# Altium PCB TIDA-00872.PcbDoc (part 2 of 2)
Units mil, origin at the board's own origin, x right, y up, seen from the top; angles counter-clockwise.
Board outline 2300 x 2250 mil, 2 copper layers (Top Layer, Bottom Layer), stack 64.8 mil thick; 81 components, 62 nets, 253 pads, 305 vias.
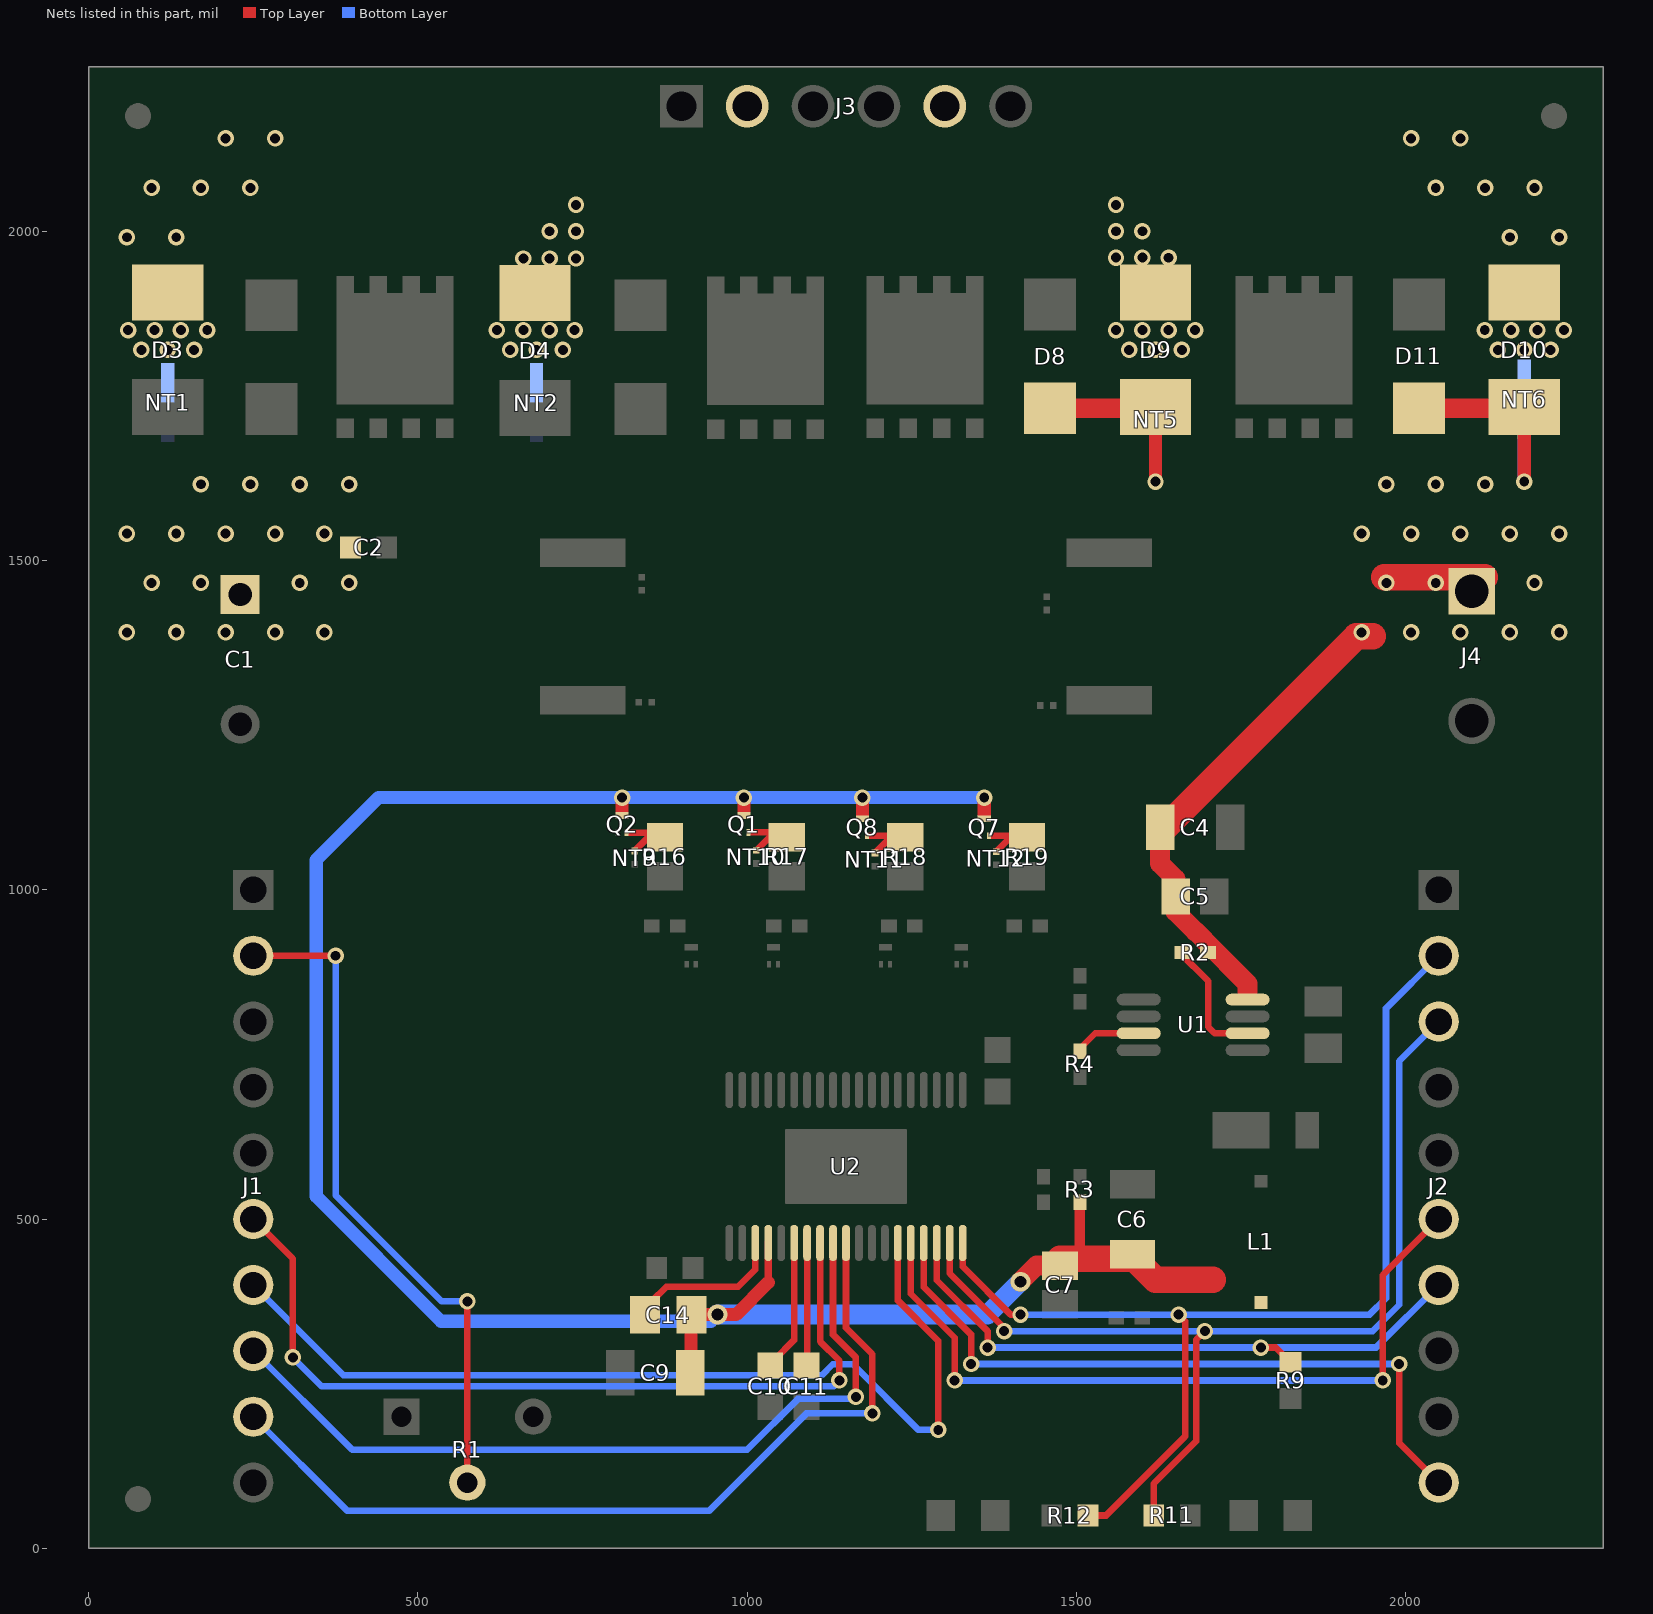
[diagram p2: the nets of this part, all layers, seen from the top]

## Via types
v1: diameter 25, hole 15, Top Layer to Bottom Layer, tented both sides, 286 vias
v2: diameter 19.68, hole 7.87, Top Layer to Bottom Layer, tented both sides, 12 vias
v3: diameter 50, hole 31, Top Layer to Bottom Layer, tented both sides, 2 vias
v4: diameter 26, hole 15, Top Layer to Bottom Layer, tented both sides, 2 vias
v5: diameter 30, hole 18, Top Layer to Bottom Layer, tented both sides, 2 vias
v6: diameter 25, hole 15, Top Layer to Bottom Layer, 1 vias

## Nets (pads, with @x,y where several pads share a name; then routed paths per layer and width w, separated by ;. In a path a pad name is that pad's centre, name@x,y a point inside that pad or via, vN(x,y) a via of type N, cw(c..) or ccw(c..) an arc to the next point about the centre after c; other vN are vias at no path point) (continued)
NetD8_1: D8.1 D9.1 NT5.1 | length 293.4
  Top Layer w20: D9.1@1618.27,1731.26 D9.1@1620,1732.99 ; v1(1620,1620) 1620,1688.99
  Top Layer w30: D8.1@1460,1731.26 D9.1@1618.27,1731.26
  Bottom Layer w20: v1(1620,1620) 1620,1630 NT5.1@1619.99,1683.7
NetD10_1: D10.1 D11.1 NT6.2 | length 337.2
  Top Layer w20: D10.1@2178.27,1731.26 D10.1@2180,1732.99 v1(2180,1620)
  Top Layer w30: D11.1@2020,1731.26 D10.1@2178.27,1731.26
  Bottom Layer w20: v1(2180,1620) 2180,1683.5
NetNT9_2: NT9.2 Q2.2 R16.2 | length 115.8
  Top Layer w6: R16.2@849.53,1079.53 R16.2@875,1079.53 R16.2@867.32,1087.2
  Top Layer w10: Q2.2@819,1087 R16.2@869.43,1087 ; NT9.2@829,1059 R16.2@849.53,1079.53
NetNT10_2: NT10.2 Q1.2 R17.2 | length 93.1
  Top Layer w10: 1006.54,1087.2 R17.2@1041.2,1087.2 ; NT10.2@1014,1060 R17.2@1041.2,1087.2 ; R17.2@1060,1090 1044,1090 R17.2@1041.2,1087.2
NetNT11_2: NT11.2 Q8.2 R18.2 | length 83.5
  Top Layer w10: Q8.2@1184.54,1082 R18.2@1220,1082 ; NT11.2@1194,1056 R18.2@1220,1082 ; R18.2@1228,1090 R18.2@1220,1082
NetNT12_2: NT12.2 Q7.2 R19.2 | length 91.8
  Top Layer w10: Q7.2@1369,1082 R19.2@1400.57,1082 ; NT12.2@1378,1058 1403.11,1083.11 1410,1090 R19.2@1425,1090
NetR2_2: R2.2 U1.6 | length 195.1
  Top Layer w10: R2.2@1656.38,905 1700,861.38 1700,791.85 1709.65,782.2 U1.6@1759.84,782.2
NetR4_2: R4.2 U1.3 | length 99.3
  Top Layer w10: R4.2@1505,758.62 1528.58,782.2 U1.3@1594.49,782.2
NFAULT: J2.3 R11.2 U2.18 | length 1558.5
  Top Layer w10: U2.18@1307.48,470.75 1307.48,417.52 1390,335 v1(1390,330) ; R11.2@1617.44,50 1617.44,98.4 1682,162.96 1682,317 v1(1695,330)
  Bottom Layer w10: v1(1390,330) v1(1695,330) 1950,330 1990,370 1990,740 J2.3@2050,800
NSLEEP: J1.6 U2.8 | length 1314.7
  Top Layer w10: J1.6@250,500 310,440 v1(310,290) ; U2.8@1110.63,470.75 1110.63,314.37 1140,285 v1(1140,255)
  Bottom Layer w10: v1(310,290) 354,246 1131,246 v1(1140,255)
NSTALL: J2.2 R12.1 U2.19 | length 1660.7
  Top Layer w10: U2.19@1327.17,470.75 1327.17,427.83 1400,355 v1(1415,355) ; R12.1@1522.56,50 1545,50 1665,170 1665,345 v1(1655,355)
  Bottom Layer w10: v1(1415,355) 1945,355 1970,380 1970,820 J2.2@2050,900
POT: J1.2 R1.2 | length 1030.6
  Top Layer w10: J1.2@250,900 v1(375,900) ; R1.2@575,100 v1(575,375)
  Bottom Layer w10: v1(375,900) 375,536.11 536.11,375 v1(575,375)
RESET: J1.8 U2.9 | length 1270.4
  Top Layer w10: U2.9@1130.31,475.75 1130.31,324.69 1165,290 v1(1165,230)
  Bottom Layer w10: J1.8@250,300 400,150 1000.11,150 1077.11,227 1162,227 v1(1165,230)
SCLK: J1.7 U2.14 | length 1460.9
  Top Layer w10: U2.14@1228.74,470.75 1228.74,376.26 1290,315 v1(1290,180)
  Bottom Layer w10: J1.7@250,400 387,263 1113.35,263 1129.85,279.5 1160.5,279.5 1260,180 v1(1290,180)
SCS: J2.10 U2.16 | length 1070.4
  Top Layer w10: U2.16@1268.11,470.75 1268.11,396.89 1340,325 v1@1340,285 ; v1(1990,280) 1990,160 J2.10@2050,100
  Bottom Layer w10: v1(1340,280) v1(1990,280)
SDATI: J2.6 U2.15 | length 1173.5
  Top Layer w10: U2.15@1248.43,470.75 1248.43,386.57 1315,320 v1(1315,255) ; v1(1965,255) 1965,415 J2.6@2050,500
  Bottom Layer w10: v1(1315,255) v1(1965,255)
SDATO: J2.7 R9.1 U2.17 | length 966.4
  Top Layer w10: U2.17@1287.8,470.75 1287.8,407.2 1365,330 v1@1365,315 ; v1(1780,305) 1802.56,305 R9.1@1825,282.56
  Bottom Layer w10: v1(1365,305) v1(1780,305) 1955,305 J2.7@2050,400
STEP/AIN1: J1.9 U2.10 | length 1342.9
  Top Layer w10: U2.10@1150,470.75 1150,335 1190,295 v1(1190,205)
  Bottom Layer w10: J1.9@250,200 393,57 942,57 1090,205 v1(1190,205)
V5: C10.1 U2.6 | length 211.7
  Top Layer w10: C10.1@1041,271.56 1041,286 1071.26,316.26 U2.6@1071.26,463.86 U2.6@1071.26,470.75
V12: C6.1 C7.1 C9.1 C14.2 L1.2 Q1.3 Q2.3 Q7.3 Q8.3 R3.2 U2.4 | length 3508.2
  Top Layer w12: 1031.89,403.89 U2.4@1031.89,463.86
  Top Layer w16: 1505,441.5 R3.2@1505,525.31
  Top Layer w20: 810,1119.41 v1(810,1140) ; C9.1@918.15,275 914.53,278.62 914.53,355 v5(955,355) 983,355 1031.89,403.89 ; 995,1119.41 v1(995,1140) ; 1175,1114.41 v1(1175,1140) ; 1360,1114.41 v1(1360,1140)
  Top Layer w30: v5(1415,405) 1439.53,429.53 C7.1@1475,429.53
  Top Layer w40: C7.1@1475,440 1587.91,440 1619.91,408 1707,408
  Bottom Layer w20: v5(955,355) 945,345 535,345 345.5,534.5 345.5,1045.5 440,1140 v1(810,1140) v1(995,1140) v1(1175,1140) v1(1360,1140)
  Bottom Layer w30: v5(955,355) 1365,355 v5(1415,405)
VCP: C14.1 U2.3 | length 244.5
  Top Layer w10: C14.1@855.47,355 855.47,375.47 877.27,397.27 986.16,397.27 1012.2,423.32 U2.3@1012.2,463.86 U2.3@1012.2,470.75
VINT: C11.1 U2.7 | length 197.2
  Top Layer w10: C11.1@1090.94,273.5 U2.7@1090.94,470.75
VM: C1.1 C2.1 C4.1 C5.1 D3.2 D4.2 D9.2 D10.2 J3.2 J3.5 J4.1 NT1.2 NT2.1 NT5.2 NT6.1 R2.1 U1.8 | length 928.5
  Top Layer w20: D9.2@1620,1880.87 D9.2@1620,1907.01
  Top Layer w30: C4.1@1626.85,1095 1626.85,1040 1650.47,1016.38 C5.1@1650.47,990 1650.47,966.85 1680.48,936.84 1681.24,936.84 1694.13,923.96 1694.13,923.19 1759.84,857.48 1759.84,843.92
  Top Layer w40: C4.1@1626.85,1095 1635,1095 1925,1385 1950,1385 ; v1@1967.25,1474.68 J4.1@2119.69,1474.68
  other v1: 58,1391 133,1391 208,1391 283,1391 358,1391 1933,1391 2008,1391 2083,1391 2158,1391 2233,1391 95.5,1466 170.5,1466 320.5,1466 395.5,1466 1970.5,1466 2045.5,1466 2195.5,1466 58,1541 133,1541 208,1541 283,1541 358,1541 1933,1541 2008,1541 2083,1541 2158,1541 2233,1541 170.5,1616 245.5,1616 320.5,1616 395.5,1616 1970.5,1616 2045.5,1616 2120.5,1616 80,1820 120,1820 160,1820 640,1820 680,1820 720,1820 1580,1820 1620,1820 1660,1820 2140,1820 2180,1820 2220,1820 60,1850 100,1850 140,1850 180,1850 620,1850 660,1850 700,1850 738,1850 1560,1850 1600,1850 1640,1850 1680,1850 2120,1850 2160,1850 2200,1850 2240,1850 660,1958.73 700,1958.73 740,1958.73 1560,1960 1600,1960 1640,1959.76 58,1991 133,1991 2158,1991 2233,1991 700,2000 740,2000 1560,2000 1600,2000 740,2040 1560,2040 95.5,2066 170.5,2066 245.5,2066 2045.5,2066 2120.5,2066 2195.5,2066 208,2141 283,2141 2008,2141 2083,2141
pads on no net: FID1.1 FID2.1 FID3.1 J1.3 J1.4 J1.5 J2.4 J2.5

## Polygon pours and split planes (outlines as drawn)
VM on Bottom Layer "Bottom Layer-No Net" (solid, remove dead copper, shelved, pour order 26): 1247.07,2030 1347.07,2030 1347.07,2150 1247.07,2150
VM on Bottom Layer "Bottom Layer-No Net" (solid, remove dead copper, shelved, pour order 29): 950,2030 1050,2030 1050,2150 950,2150
VM on Bottom Layer "VM_BOT" (solid, remove dead copper, pour order 30): 15.49,2250 15.49,1365 425,1365 425,1680 1920,1680 1920,1365 1935,1365 2300,1365 2300,2250
GND on Bottom Layer "GND_BOT" (solid, remove dead copper, pour order 31): 0,2234.46 2300,2234.46 2300,-15.54 0,-15.54
GND on Top Layer "GND_TOP" (solid, remove dead copper, pour order 32): 0,2250 2300,2250 2300,0 0,0
VM on Top Layer "Top Layer-No Net" (solid, remove dead copper, pour order 17): 198.5,2250 478.5,2250 195,1966.5 195,1665 360,1665 415,1610 415,1365 198.5,1365 0,1365 0,2250
VM on Top Layer "Top Layer-No Net" (solid, remove dead copper, pour order 18): 758.5,1943.97 758.5,1800 601.5,1800 601.5,1943.97 617.47,1943.97 758.5,2085
VM on Top Layer "Top Layer-No Net" (solid, remove dead copper, pour order 19): 1698.5,1945 1698.5,1800 1541.5,1800 1541.5,1945 1535,2090 1680,1945
VM on Top Layer "Top Layer-No Net" (solid, remove dead copper, pour order 20): 2258.5,1945 2258.5,1800 2101.5,1800 2101.5,1945
MTR_A2 on Top Layer "Top Layer-No Net 1" (solid, remove dead copper, pour order 23): 1140,1734.7 896.29,1734.9 896.29,1785.4 768.89,1785.4 768.89,2098.89 810.39,2140.39 1035,2150 1035,2230 1142.16,2230 1142.16,2056 1140,2053.84
MTR_A1 on Top Layer "Top Layer-No Net 1" (solid, remove dead copper, pour order 25): 575,1734.87 227.25,1735.16 215,1722.91 214.29,1723.62 214.29,1970.24 291,2046.95 479.05,2235 946.48,2235 946.48,2150 800,2150 614.26,1964.26 575,1964.26 575,1935.79
GND_A on Top Layer "Top Layer-No Net 2" (solid, remove dead copper, pour order 27): 375,1715 375,1675 560,1490 900,1490 1080,1670 1080,1715 940,1715 890,1665 605,1665 600,1665 550,1715
GND_B on Top Layer "Top Layer-No Net 2" (solid, remove dead copper, pour order 28): 1180,1715 1180,1675 1365,1490 1705,1490 1885,1670 1885,1715 1745,1715 1695,1665 1410,1665 1405,1665 1355,1715
VM on Top Layer "Top Layer-No Net" (solid, remove dead copper, pour order 21): 2100,2250 1820,2250 2106,1964 2106,1665 1920.87,1665 1920.87,1365 2100,1365 2298.5,1365 2298.5,2250
MTR_B2 on Top Layer "Top Layer-No Net 1" (solid, remove dead copper, pour order 24): 1719.96,1735 2067.71,1735.3 2079.96,1723.04 2080.67,1723.75 2080.67,1970.37 2003.96,2047.08 1815.91,2235.13 1348.48,2235.13 1348.48,2150.13 1494.96,2150.13 1680.7,1964.39 1719.96,1964.39 1719.96,1935.92
MTR_B1 on Top Layer "Top Layer-No Net 1" (solid, remove dead copper, pour order 22): 1155,1735 1401.5,1735.21 1401.5,1785.7 1526.11,1785.7 1526.11,2099.2 1484.61,2140.69 1260,2150.3 1260,2230.3 1152.84,2230.3 1152.84,2056.3 1155,2054.15

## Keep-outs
Keep-Out Layer:
  lines w20: -10,0 ccw(c0,0) 0,-10 ; -10,0 ccw(c0,0) 0,-10 ; -10,0 -10,2250 ; -10,2250 cw(c0,2250) 0,2260 ; -10,2250 cw(c0,2250) 0,2260 ; 0,-10 2300,-10 ; 0,2260 2300,2260 ; 2300,-10 ccw(c2300,0) 2310,0 ; 2300,-10 ccw(c2300,0) 2310,0 ; 2300,2260 cw(c2300,2250) 2310,2250 ; 2300,2260 cw(c2300,2250) 2310,2250 ; 2310,0 2310,2250
  text ".Layer_Name" at 577,-858.49 h60

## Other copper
Top Layer:
  text ".Layer_Name" at 577,-858.49 h60
Bottom Layer:
  text ".Layer_Name" at 577,-858.49 h60

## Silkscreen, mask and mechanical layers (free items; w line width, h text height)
Top Overlay:
  lines w7: 954,2055 954,2135 ; 1049,2055 1049,2135 ; 1149,2055 1149,2135 ; 1246,2055 1246,2135 ; 1345,2055 1345,2135 ; 1446,2055 864,2055 864,2135 1447,2135 ; 1447,2054 1447,2134 ; 1840,1367 1920,1367 ; 1840,1217 1840,1477 1920,1477 1920,1217 1840,1217
  text ".PRJ_Number" at 1510,2170 h40
  text "Rev." at 1900,2170 h40
  text ".PCB_Rev" at 2060,2170 h40
  text "Unipolar Config." at 1510,2110 h40
  text "A1" at 884,2075 h40
  text "VM" at 970,2075 h40
  text "A2" at 1069,2075 h40
  text "B1" at 1177,2075 h40
  text "VM" at 1259,2075 h40
  text "B2" at 1366,2075 h40
  text "VM" at 1860,1457 h40 r270
  text "GND" at 1860,1347 h40 r270
  text "GND-STL-FLT" at 1955,1050 h28 r270
  text "3.3-POT" at 319.51,1047.48 h28 r270
  text "DRV8711" at 440,590 h60
  text "SLP-CLK-RST-STP-DIR" at 320,555 h28 r270
  text "SDI-SDO-B1-B2-SCS" at 2115,525 h28 r270
  text "STALL" at 1230,100 h40
  text "FAULT" at 1710,100 h40
  text ".Layer_Name" at 577,-858.49 h60
Bottom Overlay:
  text ".Layer_Name" at 577,-858.49 h60
Top Paste:
  text ".Layer_Name" at 577,-858.49 h60
Bottom Paste:
  text ".Layer_Name" at 577,-858.49 h60
Top Solder:
  text ".Layer_Name" at 577,-858.49 h60
  text ".Layer_Name" at 577,-858.49 h60
Bottom Solder:
  text ".Layer_Name" at 577,-858.49 h60
Drill Guide:
  text ".Layer_Name" at 577,-858.49 h60
M1 Board Outline:
  the board outline again, w10
  text ".Layer_Name" at 577,-858.49 h60
M2 Board Dimensions:
  rectangle: 124.5,-410.5 499.5,-285.5
  rectangle: -0.5,-285.5 124.5,-160.5
  lines w7: -0.5,-285.5 999.5,-285.5 ; 124.5,-410.5 124.5,-160.5 ; 249.5,-410.5 249.5,-160.5 ; 499.5,-410.5 499.5,-160.5 ; 749.5,-410.5 749.5,-160.5 ; -0.5,-410.5 -0.5,-160.5 999.5,-160.5 999.5,-410.5 -0.5,-410.5
  lines w10: -0.5,-475.5 -0.5,-455.5 ; 59.5,-485.5 -0.5,-465.5 ; 59.5,-445.5 -0.5,-465.5 ; 223.58,-465.5 -0.5,-465.5 ; 775.42,-465.5 999.5,-465.5 ; 939.5,-485.5 999.5,-465.5 ; 939.5,-445.5 999.5,-465.5 ; 999.5,-475.5 999.5,-455.5
  text "1000 (mil)" at 233.58,-501.49 h60
  text ".Layer_Name" at 577,-858.49 h60
M3 3D STEP Top:
  text ".Layer_Name" at 577,-858.49 h60
M4 3D STEP Bottom:
  text ".Layer_Name" at 577,-858.49 h60
M5 Assembly Top:
  lines w10: -292,-930.17 6308,-930.17 ; -292,-726.83 6310,-726.83 ; -292,-523.5 -292,-1133.5 3713,-1133.5 6310,-1133.5 6310,-523.5 -291.5,-523.5 -291.5,-1133.5 1284,-1133.5 ; 2173,-1133.5 2173,-523.5 ; 3440,-726.83 3440,-523.5 ; 4280,-726.83 4280,-523.5 ; 4902,-1140 4902,-937.17
  text "COMPONENTS MARKED 'DNP' SHOULD NOT BE POPULATED." at 1153.5,-318.5 h60
  text "ASSEMBLY VARIANT:" at 1153,-434 h60
  text ".VariantName" at 2189,-434 h60
  text "PCB VIEWED FROM TOP SIDE" at -228.5,-655.67 h60
  text "BOARD #:" at 2248,-655.67 h60
  text ".PRJ_Number" at 2793.5,-655.67 h60
  text "REV:" at 3638,-655.67 h60
  text ".PCB_Rev" at 3929.5,-655.67 h60
  text "SVN REV:" at 4476,-655.67 h60
  text ".VersionControl_RevNumber" at 4982,-655.67 h60
  text "IGNORE ->" at -228.5,-858.49 h60
  text "PLOT NAME =" at -228.5,-1064.34 h60
  text ".plot_File_Name" at 577,-1064.34 h60
  text "GENERATED    :" at 2250,-1064.34 h60
  text ".Print_Date" at 3119.5,-1064.34 h60
  text ".Print_Time" at 3848.5,-1064.34 h60
  text "TEXAS INSTRUMENTS" at 5113,-1064.34 h60
M6 Assembly Bottom:
  lines w10: -292.5,-727.33 6309.5,-727.33 ; -290.5,-930.67 6309.5,-930.67 ; 1115.5,-1140.5 1115.5,-937.67 ; 1737.5,-727.33 1737.5,-524 ; 2577.5,-727.33 2577.5,-524 ; 3844.5,-1134 3844.5,-524 ; 4733.5,-1134 6309,-1134 6309,-524 -292.5,-524 -292.5,-1134 2304.5,-1134 6309.5,-1134 6309.5,-524
  text "COMPONENTS MARKED 'DNP' SHOULD NOT BE POPULATED." at 6102,-318 h60
  text ".VariantName" at 5058,-434 h60
  text "ASSEMBLY VARIANT:" at 6097,-434 h60
  text ".VersionControl_RevNumber" at 1035.5,-656.17 h60
  text "SVN REV:" at 1541.5,-656.17 h60
  text ".PCB_Rev" at 2088,-656.17 h60
  text "REV:" at 2379.5,-656.17 h60
  text ".PRJ_Number" at 3224,-656.17 h60
  text "BOARD #:" at 3769.5,-656.17 h60
  text "PCB VIEWED FROM BOTTOM SIDE" at 6246,-656.17 h60
  text "IGNORE ->" at 2547.85,-858.49 h60
  text "TEXAS INSTRUMENTS" at 904.5,-1064.84 h60
  text ".Print_Time" at 2169,-1064.84 h60
  text ".Print_Date" at 2898,-1064.84 h60
  text "GENERATED    :" at 3767.5,-1064.84 h60
  text ".plot_File_Name" at 5440.5,-1064.84 h60
  text "PLOT NAME =" at 6246,-1064.84 h60
M9 Title Sheet:
  drawing of 57 lines, arcs and shapes, not listed
  text "1" at 739.84,8036.5 h70
  text "2" at 3235.5,8036.5 h70
  text "3" at 5724.84,8036.5 h70
  text "4" at 8231.51,8036.5 h70
  text "5" at 10730.5,8036.5 h70
  text "6" at 13235.5,8036.5 h70
  text "A" at -416.5,6893.5 h70
  text "A" at 14383.5,6893.5 h70
  text "B" at -416.5,4513.5 h70
  text "B" at 14383.5,4513.5 h70
  text "C" at -416.5,2138.5 h70
  text "C" at 14383.5,2138.5 h70
  text "PROJECT TITLE:" at 11343.5,277.5 h45
  text ".PRJ_Title" at 11393.5,144.17 h70
  text "DESIGNED FOR:" at 11343.5,-23.5 h45
  text ".PRJ_Customer" at 11393.5,-163.5 h70
  text "D" at -416.5,-231.5 h70
  text "D" at 14383.5,-231.5 h70
  text "FILE NAME:" at 11343.5,-323.5 h45
  text ".PCB_File_Name_No_Path" at 11393.5,-443.5 h70
  text "Texas Instruments (TI) and/or its licensors do not warrant the accuracy or completeness of this specification" at 6374,-605.34 h45
  text "ENGINEER:" at 11343.5,-613.5 h45
  text "LAYOUT BY:" at 12848.5,-613.5 h45
  text "or any information contained therein. TI and/or its licensors do not warrant that this design will meet" at 6329.01,-718 h45
  text ".PRJ_Engineer" at 11393.5,-768.49 h70
  text ".PCB_Layout" at 12899,-768.49 h70
  text "the specifications, will be suitable for your application or fit for any particular purpose, or will operate in" at 6329.01,-830.67 h45
  text ".Layer_Name" at 577,-858.49 h60
  text "ALTIUM DESIGNER VERSION:" at 12848.5,-923.5 h45
  text "an implementation. TI and/or its licensors do not warrant that the design is production worthy. You should" at 6329.01,-943.33 h45
  text "completely validate and test your design implementation to confirm the system functionality for your application." at 6374,-1056 h45
  text ".print_Scale" at 11393.5,-1056.83 h70
  text ".Application_BuildNumber" at 12899,-1056.83 h70
  text "1" at 739.84,-1263.5 h70
  text "2" at 3235.5,-1263.5 h70
  text "3" at 5724.84,-1263.5 h70
  text "4" at 8231.51,-1263.5 h70
  text "5" at 10730.5,-1263.5 h70
  text "6" at 13235.5,-1263.5 h70
M10 Fab Notes:
  drawing of 189 lines, arcs and shapes, not listed
  text "DESIGN INFORMATION" at 12381.52,6022 h60
  text "MIN. TRACK WIDTH:" at 11736.96,5842 h60
  text "8" at 12833.2,5842 h60
  text "MIL" at 12987.96,5842 h60
  text "MIN. CLEARANCE:" at 11736.96,5710 h60
  text "0.2" at 12773.2,5710 h60
  text "mm" at 12987.96,5710 h60
  text "MIN. VIA PAD SIZE:" at 11736.96,5578 h60
  text "24" at 12803.21,5578 h60
  text "MIL" at 12987.96,5578 h60
  text "0.05mm (2MIL)" at 12431.96,5436.29 h60
  text "MINIMUM ANNULAR RING" at 11407.73,5432 h60
  text "EXTERNAL" at 13139.96,5432 h60
  text "PER" at 11607.73,5314 h60
  text "IPC-D-275 CLASS 2 LEVEL C" at 11827.73,5314 h60
  text "MIL, HOLES" at 13315.96,5201.71 h60
  text "+/-" at 12923.5,5201 h60
  text "+/-" at 13777.5,5201 h60
  text "REGISTRATION TOLERANCES:" at 11407.73,5196 h60
  text "METAL" at 12607.5,5196 h60
  text "5" at 13183.7,5196 h60
  text "3" at 14016.7,5196 h60
  text "MIL" at 14132.96,5196 h60
  text "+/-" at 13777.5,5083 h60
  text "HOLE SIZE TOLERANCE (UNLESS OTHERWISE SPECIFIED):" at 11407.73,5078 h60
  text "3" at 14016.7,5078 h60
  text "MIL" at 14132.96,5078 h60
  text "MATERIAL:" at 11332.96,4868.54 h60
  text "FR-4 High Tg" at 12319.4,4728.21 h60
  text "FR-408" at 11753.96,4719.64 h60
  text "OTHER" at 13241.96,4719.64 h60
  text "X" at 12164.5,4716 h60
  text "62 MIL (1.6mm) +/-10%" at 12074.06,4556.92 h60
  text "THICKNESS:" at 11407.73,4552.64 h60
  text "X" at 11945.9,4552.64 h60
  text "OTHER" at 13358.96,4552.64 h60
  text "TOLERANCE:" at 11407.73,4394.64 h60
  text "X" at 12247.03,4394.64 h60
  text "ANSI IPC-6012 TYPE 3 CLASS 2" at 12433.98,4394.64 h60
  text "OTHER +/-" at 12433.96,4238.64 h60
  text "BOW & TWIST:" at 11407.73,4081.64 h60
  text "X" at 12247.03,4081.64 h60
  text "ANSI IPC-6012 TYPE 3 CLASS 2" at 12433.98,4081.64 h60
  text "OTHER +/-" at 12433.96,3923.13 h60
  text "DRILLING:" at 11332.96,3784.64 h60
  text "REFERENCE:" at 11407.73,3667.64 h60
  text "X" at 12055.96,3667.64 h60
  text "AS SHOWN" at 12242.96,3667.64 h60
  text "X" at 12956.96,3667.64 h60
  text "NC_DRILL FILES" at 13093.96,3667.64 h60
  text "PTH MIN COPPER THICKNESS:" at 11407.73,3509.64 h60
  text "X" at 12757.96,3509.64 h60
  text "1MIL" at 12894.96,3509.64 h60
  text "OTHER" at 13391.96,3509.64 h60
  text "BOARD FINISH:" at 11332.96,3350.64 h60
  text "SILKSCREEN:" at 11488.18,3232.64 h60
  text "X" at 12436.96,3232.64 h60
  text "TOP" at 12562.96,3232.64 h60
  text "BOTTOM" at 13073.96,3232.64 h60
  text "SILKSCREEN COLOR:" at 11488.18,3065.64 h60
  text "X" at 12435.92,3065.64 h60
  text "WHITE" at 12562.96,3065.64 h60
  text "OTHER" at 13073.96,3065.64 h60
  text "RED" at 13673.96,2910.64 h60
  text "X" at 13160,2910 h60
  text "GREEN" at 12693.96,2906.44 h60
  text "OTHER" at 13311.96,2906.44 h60
  text "SOLDER RESIST COLOR:" at 11488.18,2895.64 h60
  text "X" at 12566.92,2736.44 h60
  text "MATTE" at 12693.96,2736.44 h60
  text "SEMI-GLOSS" at 13311.5,2735.8 h60
  text "IMMERSION GOLD (ENIG)" at 12393.96,2547.92 h60
  text "ENEPIG" at 13731.5,2544.64 h60
  text "SURFACE FINISH:" at 11332.96,2543.64 h60
  text "X" at 12207.01,2543.64 h60
  text "IMM. TIN/SILVER OR EQUIV" at 11662.5,2386.64 h60
  text "OTHER" at 13093.96,2386.64 h60
  text "ARRAY/PANEL:" at 11332.96,2207.64 h60
  text "CUT AND TRIM PER M1 BOARD OUTLINE" at 12393.96,2203.35 h60
  text "N.C. ROUTE" at 12393.96,2051.64 h60
  text "X" at 13072.96,2051.64 h60
  text "V. SCORE" at 13259.96,2051.64 h60
  text "CERTIFICATION:" at 11332.96,1914.64 h60
  text "MATERIALS AND WORKMANSHIP FOR ALL PCBS" at 12057.96,1914.64 h60
  text "TO MEET OR EXCEED THE REQUIREMENTS OF:" at 12057.96,1816.64 h60
  text "X" at 11684.46,1680.13 h60
  text "ANSI IPC-A-600F CLASS ->" at 11823.46,1680.13 h60
  text "X" at 13462.52,1680.13 h60
  text "2" at 13581.46,1680.14 h60
  text "1" at 13266.46,1678.64 h60
  text "3" at 13935.46,1678.64 h60
  text "X" at 11686.52,1520.64 h60
  text "UL 94V-0" at 11823.46,1520.64 h60
  text "X" at 12498.52,1520.64 h60
  text "RoHS" at 12635.46,1520.64 h60
  text "OTHER" at 13279.86,1520.64 h60
  text "PER ORDER" at 13676.92,1520.64 h60
  text "ADDITIONAL REQUIREMENTS:" at 11332.96,1379.64 h60
  text "MICROSECTION:" at 11407.73,1264.64 h60
  text "YES" at 12313.46,1264.64 h60
  text "REQUIRED" at 13174.96,1108.49 h60
  text "BARE BOARD ELEC. TEST:" at 11407.73,1105.64 h60
  text "NONE" at 12713.46,1105.64 h60
  text "X" at 13047.96,1105.64 h60
  text "PER ORDER" at 13766.96,1105.64 h60
  text "MANUFACTURER'S UL:" at 11407.73,948.64 h60
  text "RAIL" at 12573.46,944.35 h60
  text "METAL" at 13065.27,944.35 h60
  text "X" at 13440.5,944 h60
  text "SILK" at 13576.96,944.35 h60
  text ".Layer_Name" at 577,-858.49 h60
M11 Gerber Information:
  lines w10: -292,-930.17 6308,-930.17 ; -292,-726.83 6310,-726.83 ; -292,-523.5 -292,-1133.5 3713,-1133.5 6310,-1133.5 6310,-523.5 -291.5,-523.5 -291.5,-1133.5 1284,-1133.5 ; 2173,-1133.5 2173,-523.5 ; 3440,-726.83 3440,-523.5 ; 4280,-726.83 4280,-523.5 ; 4902,-1140 4902,-937.17
  text "ALL ARTWORK VIEWED FROM TOP SIDE" at -228.5,-655.67 h60
  text "BOARD #:" at 2248,-655.67 h60
  text ".PRJ_Number" at 2793.5,-655.67 h60
  text "REV:" at 3638,-655.67 h60
  text ".PCB_Rev" at 3929.5,-655.67 h60
  text "SVN REV:" at 4476,-655.67 h60
  text ".VersionControl_RevNumber" at 4982,-655.67 h60
  text "LAYER NAME =" at -228.5,-858.49 h60
  text "PLOT NAME =" at -228.5,-1064.34 h60
  text ".plot_File_Name" at 577,-1064.34 h60
  text "GENERATED    :" at 2250,-1064.34 h60
  text ".Print_Date" at 3119.5,-1064.34 h60
  text ".Print_Time" at 3848.5,-1064.34 h60
  text "TEXAS INSTRUMENTS" at 5113,-1064.34 h60
M12 Stackup:
  drawing of 165 lines, arcs and shapes, not listed
  text "Layer" at 9850.55,7840 h60
  text "Name" at 10260.47,7840 h60
  text "Material" at 11120.23,7840 h60
  text "Thickness" at 11980,7840 h60
  text "Constant" at 12629.84,7840 h60
  text "Board Layer Stack" at 13199.7,7840 h60
  text "1" at 9850.55,7720 h60
  text "Top Overlay" at 10260.47,7720 h60
  text "2" at 9850.55,7600 h60
  text "Top Solder" at 10260.47,7600 h60
  text "Solder Resist" at 11120.23,7600 h60
  text "0.40mil" at 11980,7600 h60
  text "3.5" at 12629.84,7600 h60
  text "3" at 9850.55,7480 h60
  text "Top Layer" at 10260.47,7480 h60
  text "Copper" at 11120.23,7480 h60
  text "2.80mil" at 11980,7480 h60
  text "4" at 9850.55,7360 h60
  text "Dielectric1" at 10260.47,7360 h60
  text "FR-4" at 11120.23,7360 h60
  text "59.20mil" at 11980,7360 h60
  text "4.8" at 12629.84,7360 h60
  text "5" at 9850.55,7240 h60
  text "Bottom Layer" at 10260.47,7240 h60
  text "Copper" at 11120.23,7240 h60
  text "2.80mil" at 11980,7240 h60
  text "6" at 9850.55,7120 h60
  text "Bottom Solder" at 10260.47,7120 h60
  text "Solder Resist" at 11120.23,7120 h60
  text "0.40mil" at 11980,7120 h60
  text "3.5" at 12629.84,7120 h60
  text ".Layer_Name" at 577,-858.49 h60
M13 Component Bodies Top:
  text ".Layer_Name" at 577,-858.49 h60
M14 Component Bodies Bottom:
  text ".Layer_Name" at 577,-858.49 h60
M15 Courtyards Top:
  text ".Layer_Name" at 577,-858.49 h60
M16 Courtyards Bottom:
  text ".Layer_Name" at 577,-858.49 h60
Drill Drawing:
  circle w1: c3032.8,1901.37 r24.91
  lines w1: 3007.89,979.71 3007.89,992.16 3020.35,1004.62 3007.89,1017.07 3007.89,1029.53 3020.35,1029.53 3032.8,1017.07 3045.26,1029.53 3057.71,1029.53 3057.71,1017.07 3045.26,1004.62 3057.71,992.16 3057.71,979.71 3045.26,979.71 3032.8,992.16 3020.35,979.71 3007.89,979.71 ; 3007.89,1141.62 3020.35,1141.62 3020.35,1129.17 3045.26,1129.17 3045.26,1141.62 3057.71,1141.62 3057.71,1166.53 3045.26,1166.53 3045.26,1178.99 3020.35,1178.99 3020.35,1166.53 3007.89,1166.53 3007.89,1141.62 ; 3007.89,1303.54 3032.8,1278.63 3057.71,1303.54 3032.8,1328.45 3007.89,1303.54 ; 3007.89,1440.54 3020.35,1440.54 3032.8,1428.09 3045.26,1440.54 3057.71,1440.54 3045.26,1453 3057.71,1465.45 3045.26,1465.45 3032.8,1477.91 3020.35,1465.45 3007.89,1465.45 3020.35,1453 3007.89,1440.54 ; 3007.89,1577.54 3032.8,1590 3057.71,1577.54 3045.26,1602.45 3057.71,1627.36 3032.8,1614.91 3007.89,1627.36 3020.35,1602.45 3007.89,1577.54 ; 3007.89,1776.82 3057.71,1776.82 3032.8,1727 3007.89,1776.82 ; 3007.89,2025.92 3057.71,2025.92 3057.71,2075.74 3007.89,2075.74 3007.89,2025.92
  lines w12: 2940,934.87 5059.4,934.87 ; 2940,2130.54 5059.4,2130.54 ; 3310.67,785.41 3310.67,2280 ; 3667.78,785.41 3667.78,2280 ; 4329.79,785.41 4329.79,2280 ; 4614.14,785.41 4614.14,2280 ; 2940,785.41 5059.4,785.41 5059.4,2280 2940,2280 2940,785.41
  text "Symbol" at 3029.68,2175.38 h72
  text "Quantity" at 3355.51,2175.38 h72
  text "Finished Hole Size" at 3712.62,2175.38 h72
  text "Plated" at 4374.62,2175.38 h72
  text "Hole Type" at 4658.98,2175.38 h72
  text "12" at 3355.51,2025.92 h60
  text "7.87mil (0.200mm)" at 3712.62,2025.92 h60
  text "PTH" at 4374.62,2025.92 h60
  text "Round" at 4658.98,2025.92 h60
  text "289" at 3355.51,1876.46 h60
  text "15.00mil (0.381mm)" at 3712.62,1876.46 h60
  text "PTH" at 4374.62,1876.46 h60
  text "Round" at 4658.98,1876.46 h60
  text "2" at 3355.51,1727 h60
  text "18.00mil (0.457mm)" at 3712.62,1727 h60
  text "PTH" at 4374.62,1727 h60
  text "Round" at 4658.98,1727 h60
  text "5" at 3355.51,1577.54 h60
  text "31.00mil (0.787mm)" at 3712.62,1577.54 h60
  text "PTH" at 4374.62,1577.54 h60
  text "Round" at 4658.98,1577.54 h60
  text "2" at 3355.51,1428.09 h60
  text "35.43mil (0.900mm)" at 3712.62,1428.09 h60
  text "PTH" at 4374.62,1428.09 h60
  text "Round" at 4658.98,1428.09 h60
  text "20" at 3355.51,1278.63 h60
  text "40.16mil (1.020mm)" at 3712.62,1278.63 h60
  text "PTH" at 4374.62,1278.63 h60
  text "Round" at 4658.98,1278.63 h60
  text "6" at 3355.51,1129.17 h60
  text "45.28mil (1.150mm)" at 3712.62,1129.17 h60
  text "PTH" at 4374.62,1129.17 h60
  text "Round" at 4658.98,1129.17 h60
  text "2" at 3355.51,979.71 h60
  text "51.18mil (1.300mm)" at 3712.62,979.71 h60
  text "PTH" at 4374.62,979.71 h60
  text "Round" at 4658.98,979.71 h60
  text "338 Total" at 3355.51,830.25 h60
  text ".Layer_Name" at 577,-858.49 h60

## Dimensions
0,0 to 2300,0 on M2 Board Dimensions
0,0 to 0,2250 on M2 Board Dimensions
